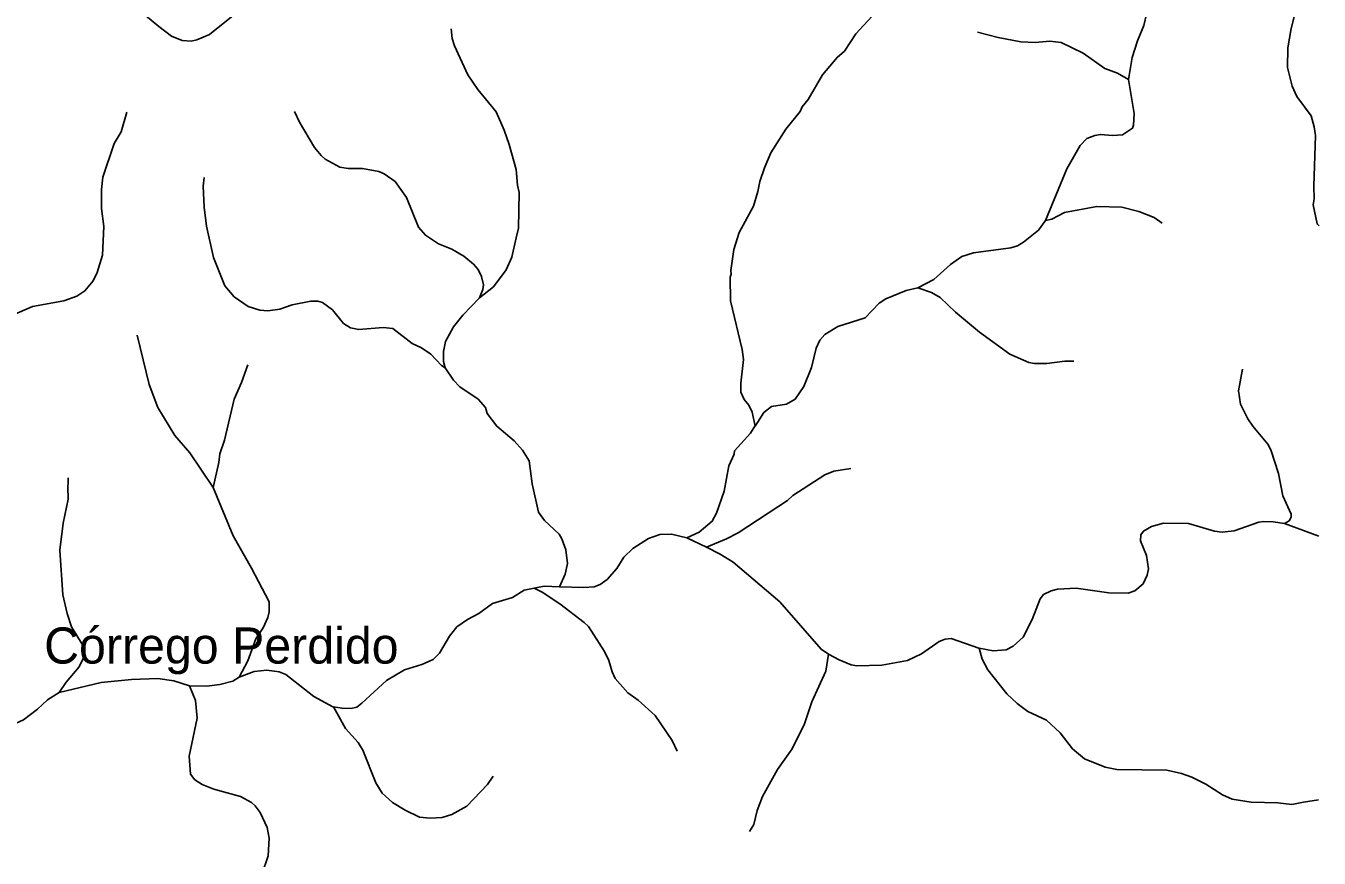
# Model space of a CAD drawing. Extents: x 500 to 555.2, y 9115.7 to 9171.
# Drawn here: x 547.99 to 555.15, y 9156.91 to 9161.52 of the extents above; entities that cross this region are included whole.
import ezdxf
from ezdxf.enums import TextEntityAlignment as Align

# ---------------------------------------------------------------- set-up
doc = ezdxf.new("R2010")
doc.units = 0
doc.header["$LTSCALE"] = 0.064
doc.layers.add('61', color=7, linetype='Continuous')
doc.layers.add('7', color=7, linetype='Continuous', lineweight=25)

msp = doc.modelspace()

# ---------------------------------------------------------------- linework, layer by layer
at = {"layer": '7'}
msp.add_line((555.1514, 9158.6937), (554.9624, 9158.7626), dxfattribs=at)
for points in [[(554.2526, 9162.1267), (554.2261, 9162.0809), (554.1983, 9161.9809), (554.19, 9161.8627), (554.208, 9161.6952), (554.1993, 9161.5919), (554.1823, 9161.5215), (554.1475, 9161.4369), (554.1176, 9161.3438), (554.0981, 9161.2224)], [(549.1685, 9161.5984), (549.0097, 9161.4717), (548.9403, 9161.4416), (548.9081, 9161.4347), (548.859, 9161.4376), (548.7996, 9161.4624), (548.7283, 9161.5147), (548.4992, 9161.7074)], [(555.1534, 9160.4111), (555.1419, 9160.4225), (555.1201, 9160.527), (555.1264, 9160.5604), (555.1233, 9160.6308), (555.1333, 9160.9116), (555.1262, 9160.9603), (555.1097, 9161.0199), (555.0302, 9161.1269), (555.0034, 9161.1844), (554.9789, 9161.2886), (554.9807, 9161.3976), (554.9985, 9161.5046), (555.0411, 9161.6725)], [(552.7226, 9161.6211), (552.5891, 9161.474), (552.5251, 9161.379), (552.4842, 9161.3445), (552.4033, 9161.2471), (552.3252, 9161.1104), (552.2909, 9161.0708), (552.2799, 9161.044), (552.2003, 9160.9474), (552.1183, 9160.8162), (552.0817, 9160.733), (552.056, 9160.6571), (552.0457, 9160.6018), (552.0214, 9160.5211), (551.9414, 9160.3738), (551.9136, 9160.2802), (551.8969, 9160.1634), (551.8983, 9160.1444), (551.8919, 9160.1267), (551.8952, 9159.9961), (551.9591, 9159.7271), (551.9669, 9159.6706), (551.9509, 9159.5395), (551.951, 9159.4899), (551.9699, 9159.4497), (551.9955, 9159.4181), (552.0146, 9159.38), (552.0303, 9159.3026)], [(550.3475, 9161.5029), (550.3535, 9161.4483), (550.3656, 9161.4075), (550.4409, 9161.2479), (550.4947, 9161.1667), (550.5964, 9161.0435), (550.6417, 9160.9415), (550.6695, 9160.8628), (550.7074, 9160.7244), (550.7142, 9160.6364), (550.7239, 9160.5964), (550.7207, 9160.3986), (550.7084, 9160.3451), (550.6843, 9160.2384), (550.6517, 9160.1681), (550.5812, 9160.0732), (550.5053, 9160.013)], [(553.2611, 9161.4833), (553.376, 9161.4541), (553.5013, 9161.4311), (553.582, 9161.4266), (553.6618, 9161.4347), (553.7251, 9161.4265), (553.8478, 9161.3669), (553.9674, 9161.2826), (554.0366, 9161.2571), (554.0981, 9161.2224)], [(554.0981, 9161.2224), (554.1292, 9161.0328), (554.1261, 9160.9688), (554.1205, 9160.952), (554.0645, 9160.9163), (554.0085, 9160.9114), (553.9422, 9160.9179), (553.9113, 9160.9126), (553.8674, 9160.8951), (553.8295, 9160.8561), (553.7563, 9160.7278), (553.6392, 9160.4409)], [(548.5521, 9161.0415), (548.5212, 9160.9317), (548.4814, 9160.8674), (548.4182, 9160.6818), (548.4112, 9160.6135), (548.4113, 9160.5074), (548.4244, 9160.4086), (548.4177, 9160.2488), (548.3881, 9160.1537), (548.3649, 9160.1071), (548.3193, 9160.052), (548.2755, 9160.0226), (548.2028, 9159.9962), (548.0292, 9159.9645), (547.7132, 9159.8279), (547.656, 9159.8106), (547.5688, 9159.7993), (547.4473, 9159.8079), (547.353, 9159.8269), (547.3052, 9159.848), (547.2828, 9159.8624)], [(549.4804, 9161.0446), (549.5077, 9160.9863), (549.5906, 9160.8459), (549.6274, 9160.8008), (549.6507, 9160.7812), (549.732, 9160.7371), (549.778, 9160.7294), (549.8565, 9160.7291), (549.9478, 9160.7125), (549.9776, 9160.6998), (550.0377, 9160.6562), (550.0999, 9160.5681), (550.1667, 9160.4042), (550.2048, 9160.3594), (550.2773, 9160.3113), (550.3506, 9160.282), (550.4172, 9160.2438), (550.471, 9160.1999), (550.4967, 9160.1701), (550.5159, 9160.131), (550.527, 9160.0841), (550.5239, 9160.0589), (550.5053, 9160.013)], [(548.9801, 9160.6784), (548.9755, 9160.6319), (548.98, 9160.5145), (548.9923, 9160.4094), (549.032, 9160.2367), (549.0948, 9160.0794), (549.1466, 9160.0186), (549.2237, 9159.9657), (549.2891, 9159.944), (549.3324, 9159.9404), (549.3992, 9159.9503), (549.4675, 9159.9731), (549.5704, 9159.9941), (549.6098, 9159.9946), (549.635, 9159.9878), (549.6906, 9159.9469), (549.7507, 9159.871), (549.7897, 9159.8468), (549.8356, 9159.8371), (549.9714, 9159.8483), (550.0243, 9159.843), (550.1313, 9159.7603), (550.1833, 9159.735), (550.2353, 9159.7008), (550.2933, 9159.6378), (550.3145, 9159.6246)], [(554.2845, 9160.4261), (554.2391, 9160.4569), (554.156, 9160.4911), (554.0603, 9160.5143), (553.9219, 9160.5192), (553.7428, 9160.485), (553.6731, 9160.4489), (553.6392, 9160.4409)], [(553.6392, 9160.4409), (553.6005, 9160.3877), (553.5163, 9160.3212), (553.4835, 9160.3016), (553.4463, 9160.2896), (553.2396, 9160.2617), (553.1747, 9160.2421), (553.1119, 9160.1972), (553.0197, 9160.1139), (552.9317, 9160.0677)], [(550.5053, 9160.013), (550.4119, 9159.9168), (550.3606, 9159.852), (550.3167, 9159.7716), (550.3058, 9159.7147), (550.3054, 9159.6603), (550.3142, 9159.625), (550.3145, 9159.6246)], [(552.9317, 9160.0677), (552.8677, 9160.0535), (552.7548, 9160.0076), (552.7182, 9159.9841), (552.6398, 9159.9028), (552.4883, 9159.8545), (552.4169, 9159.8106), (552.389, 9159.7779), (552.3679, 9159.7344), (552.3424, 9159.6272), (552.3006, 9159.5211), (552.2526, 9159.4517), (552.205, 9159.4246), (552.1217, 9159.4119), (552.0793, 9159.3774), (552.0303, 9159.3026)], [(553.7945, 9159.6624), (553.7459, 9159.6622), (553.645, 9159.6484), (553.5781, 9159.6484), (553.5454, 9159.6551), (553.4408, 9159.7016), (553.2736, 9159.8219), (553.1393, 9159.933), (553.0548, 9160.014), (553.0067, 9160.0423), (552.9317, 9160.0677)], [(548.6094, 9159.806), (548.6753, 9159.5336), (548.7244, 9159.4059), (548.8178, 9159.2499), (548.8999, 9159.1546), (549.0306, 9158.9621), (549.0307, 9158.9619)], [(549.2217, 9159.6411), (549.1875, 9159.5447), (549.1459, 9159.4509), (549.0919, 9159.2253), (549.0664, 9159.1496), (549.0607, 9159.1006), (549.0307, 9158.9619)], [(550.3145, 9159.6246), (550.3612, 9159.5569), (550.3958, 9159.5202), (550.4971, 9159.4519), (550.5385, 9159.4055), (550.5472, 9159.3727), (550.5999, 9159.3019), (550.6967, 9159.2213), (550.742, 9159.1694), (550.7793, 9159.1105), (550.7963, 9158.9818), (550.8321, 9158.8256), (550.8646, 9158.7795), (550.9453, 9158.7036), (550.9604, 9158.6783), (550.9832, 9158.6177), (550.9912, 9158.542), (550.9792, 9158.4825), (550.9472, 9158.4129)], [(554.7294, 9159.618), (554.7067, 9159.4981), (554.7185, 9159.4233), (554.7591, 9159.3434), (554.7872, 9159.3015), (554.8685, 9159.2028), (554.8852, 9159.1716), (554.929, 9159.0405), (554.9531, 9158.9155), (554.9984, 9158.8152), (554.9977, 9158.7979), (554.9872, 9158.7786), (554.9624, 9158.7626)], [(552.0303, 9159.3026), (552.0298, 9159.3019), (552.0057, 9159.2626), (551.9166, 9159.1654), (551.9144, 9159.1477), (551.8857, 9159.0822), (551.8587, 9158.9424), (551.8169, 9158.8198), (551.7928, 9158.7753), (551.72, 9158.7158), (551.653, 9158.6839)], [(548.2274, 9159.0168), (548.2267, 9158.9889), (548.2258, 9158.9655), (548.2274, 9158.8972), (548.2, 9158.7646), (548.1816, 9158.6156), (548.198, 9158.3677), (548.2212, 9158.265), (548.2451, 9158.1913), (548.3096, 9158.0862), (548.3178, 9158.0306), (548.2881, 9157.9688), (548.2162, 9157.8852), (548.1779, 9157.8276)], [(552.5603, 9159.0671), (552.467, 9159.0531), (552.4174, 9159.0318), (552.2392, 9158.9181), (552.2096, 9158.8902), (551.9372, 9158.7115), (551.8717, 9158.6775), (551.7607, 9158.6313)], [(549.0307, 9158.9619), (549.1409, 9158.6944), (549.2428, 9158.5166), (549.3396, 9158.3298), (549.3395, 9158.2739), (549.3324, 9158.243), (549.3063, 9158.1847), (549.2668, 9158.1249), (549.2225, 9158.0034), (549.1747, 9157.9123)], [(554.9624, 9158.7626), (554.8987, 9158.772), (554.8478, 9158.774), (554.8192, 9158.7712), (554.6836, 9158.7233), (554.6163, 9158.7152), (554.5748, 9158.7201), (554.4295, 9158.7627), (554.2915, 9158.7643), (554.2259, 9158.7466), (554.1804, 9158.7212), (554.1654, 9158.6995), (554.1642, 9158.6666), (554.198, 9158.5855), (554.2095, 9158.5122), (554.2013, 9158.4772), (554.1798, 9158.4297), (554.1331, 9158.3909), (554.0964, 9158.3773), (553.9889, 9158.3787), (553.8077, 9158.405), (553.7042, 9158.3986), (553.6693, 9158.39), (553.6278, 9158.3691), (553.6081, 9158.3464), (553.5654, 9158.2317), (553.5144, 9158.1333), (553.4589, 9158.0835), (553.4199, 9158.0638), (553.3477, 9158.0574), (553.2712, 9158.0729)], [(551.653, 9158.6839), (551.5678, 9158.7044), (551.5022, 9158.7019), (551.4411, 9158.6798), (551.3527, 9158.6254), (551.3031, 9158.5772), (551.2652, 9158.5134), (551.2116, 9158.4531), (551.1728, 9158.4261), (551.14, 9158.4132), (551.0831, 9158.4084), (550.9472, 9158.4129)], [(552.4375, 9158.0393), (552.396, 9158.0669), (552.1669, 9158.3301), (551.9093, 9158.5481), (551.8377, 9158.5937), (551.7607, 9158.6313), (551.653, 9158.6839)], [(550.8075, 9158.4049), (550.7518, 9158.3939), (550.6873, 9158.354), (550.577, 9158.3198), (550.5016, 9158.2649), (550.4373, 9158.232), (550.3796, 9158.1901), (550.3383, 9158.1399), (550.2831, 9158.0448), (550.2487, 9158.0101), (550.186, 9157.9819), (550.089, 9157.9528), (549.9903, 9157.8945), (549.8525, 9157.7678), (549.8251, 9157.7456), (549.7933, 9157.7378), (549.7441, 9157.7398), (549.6954, 9157.7481)], [(550.9472, 9158.4129), (550.8621, 9158.4157), (550.8075, 9158.4049)], [(551.5993, 9157.5031), (551.572, 9157.5619), (551.4764, 9157.7002), (551.3834, 9157.785), (551.3262, 9157.8257), (551.2563, 9157.9053), (551.2384, 9157.9412), (551.221, 9158.0048), (551.196, 9158.0545), (551.1078, 9158.1918), (551.0838, 9158.2154), (550.9487, 9158.3181), (550.8507, 9158.3834), (550.8075, 9158.4049)], [(548.1779, 9157.8276), (548.1131, 9157.7868), (548.0567, 9157.7342), (547.9802, 9157.6762), (547.9145, 9157.6468), (547.7558, 9157.5945), (547.6938, 9157.5854), (547.6389, 9157.5884), (547.5719, 9157.606), (547.5222, 9157.6341), (547.4791, 9157.687), (547.4619, 9157.7164), (547.4452, 9157.768), (547.4268, 9158.0152), (547.397, 9158.107), (547.3774, 9158.1315), (547.3253, 9158.1655), (547.2902, 9158.1786)], [(553.2712, 9158.0729), (553.2685, 9158.0735), (553.1162, 9158.1258), (553.0822, 9158.1229), (553.0499, 9158.1097), (552.9526, 9158.0417), (552.8745, 9158.0044), (552.7324, 9157.9786), (552.5939, 9157.9753), (552.5618, 9157.9802), (552.4962, 9158.0078), (552.4375, 9158.0393)], [(555.1497, 9157.2328), (555.0677, 9157.2189), (555.0018, 9157.2077), (554.9243, 9157.2157), (554.7762, 9157.2194), (554.6711, 9157.2355), (554.6191, 9157.2596), (554.5262, 9157.319), (554.4479, 9157.3583), (554.3914, 9157.3792), (554.3096, 9157.3962), (554.0341, 9157.4012), (553.9679, 9157.4129), (553.8548, 9157.4606), (553.7881, 9157.516), (553.7194, 9157.604), (553.6447, 9157.6737), (553.5408, 9157.7219), (553.4808, 9157.7658), (553.4234, 9157.8199), (553.3186, 9157.9529), (553.2878, 9158.0115), (553.2712, 9158.0729)], [(551.9998, 9157.0576), (552.0232, 9157.0967), (552.0425, 9157.1736), (552.0723, 9157.2504), (552.154, 9157.4007), (552.2362, 9157.5144), (552.3047, 9157.6542), (552.3449, 9157.7757), (552.4228, 9157.9461), (552.4375, 9158.0393)], [(549.6954, 9157.7481), (549.6924, 9157.7484), (549.5867, 9157.8052), (549.432, 9157.9273), (549.3946, 9157.9425), (549.328, 9157.9517), (549.257, 9157.9438), (549.1747, 9157.9123)], [(548.8987, 9157.8636), (548.8121, 9157.8914), (548.7243, 9157.9046), (548.5778, 9157.9), (548.4106, 9157.8817), (548.1779, 9157.8276)], [(549.2988, 9156.8195), (549.3347, 9156.9222), (549.3395, 9157.0212), (549.3283, 9157.0791), (549.2903, 9157.1617), (549.2623, 9157.2), (549.2419, 9157.2181), (549.1816, 9157.2515), (549.0335, 9157.2923), (548.9684, 9157.3178), (548.9279, 9157.3441), (548.9036, 9157.3753), (548.8969, 9157.4747), (548.9409, 9157.6846), (548.9325, 9157.7823), (548.8987, 9157.8636)], [(549.1747, 9157.9123), (549.1383, 9157.889), (549.0667, 9157.8718), (548.9945, 9157.8621), (548.8987, 9157.8636)], [(550.5805, 9157.363), (550.548, 9157.3171), (550.4353, 9157.1979), (550.3505, 9157.1521), (550.297, 9157.1354), (550.2319, 9157.1306), (550.172, 9157.1372), (550.0937, 9157.1752), (550.0232, 9157.2182), (549.9652, 9157.2695), (549.9313, 9157.3268), (549.8581, 9157.5073), (549.8329, 9157.5508), (549.7623, 9157.6284), (549.6954, 9157.7481)]]:
    msp.add_lwpolyline(points, dxfattribs=at)

# ---------------------------------------------------------------- texts
at = {"layer": '61'}
msp.add_text('Córrego Perdido', height=0.2, dxfattribs=at).set_placement((549.0753, 9157.9873), align=Align.CENTER)

doc.saveas('drawing.dxf')
